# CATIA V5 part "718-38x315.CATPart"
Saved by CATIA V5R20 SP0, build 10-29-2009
Part number: 718-38x315
Definition: NONE
Nomenclature: 718-38x315
Source: Unknown
Description: 718-38x315
Bounding box of the stored display mesh (mm): x 0 to 352, y -25 to 25, z -25 to 25
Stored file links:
  C:\Users\Utente\Desktop\IO LAVORO\3D X SITO CF\X SITO\718\718-38x315.CATPart

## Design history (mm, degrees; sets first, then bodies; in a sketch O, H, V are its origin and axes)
Body1 "718-38x315" (main body)
  Solid1: solid without history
